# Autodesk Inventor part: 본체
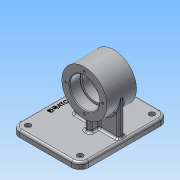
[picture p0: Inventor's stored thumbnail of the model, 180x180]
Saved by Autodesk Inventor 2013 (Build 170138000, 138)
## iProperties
Created: 2019-09
Part Number: 본체
Material: 알루미늄 6061
Document SubType Name: Modeling
Designer: Administrator
Density: 2.71 g/cm^3
Mass: 556.675 g
Surface Area: 495.884 cm^2
Volume: 205.415 cm^3
Author: Administrator
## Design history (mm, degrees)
sketch "스케치1"
  geometry: C1 r 32 at (0, 0); 1 further point
  constraints: 1 centre point, 1 coincident
  dimensions: "d0" = 64 diameter of C1
extrude "돌출1" new body sketch "스케치1" stored distance "d1" = 42; taper "d2" = 0 deg
sketch "스케치2"
  geometry: C1 r 32 at (0, 0) reference; C2 r 21 at (0, 0)
  constraints: 1 centre point, 1 coincident
  dimensions: "d3" = 42 diameter of C2
extrude "돌출2" cut sketch "스케치2" distance "d4" = 15; taper "d5" = 0 deg
sketch "스케치3"
  geometry: C1 r 21 at (0, 0) reference; C2 r 18 at (0, 0)
  constraints: 1 centre point, 1 coincident
  dimensions: "d6" = 36 diameter of C2
extrude "돌출3" cut sketch "스케치3" stored distance "d7" = 15; taper "d8" = 0 deg
sketch "스케치4"
  geometry: C1 r 32 at (0, 0) reference; C2 r 21 at (0, 0)
  constraints: 1 centre point, 1 coincident
  dimensions: "d9" = 42 diameter of C2
extrude "돌출4" cut sketch "스케치4" distance "d10" = 15; taper "d11" = 0 deg
fillet "모깎기1" dims "d12" = 0.3
chamfer "모따기1" distance "d13" = 1; stored, may be unused: second distance "d14" = 2, angle "d15" = 45 deg
sketch "스케치5"
  geometry: C1 r 32 at (0, 0) reference; 1 further point
  constraints: 1 vertical alignment
  dimensions: "d16" = 26 distance of point (0, 26) C1.centre
hole "구멍1" sketch "스케치5" at (0, 26) diameter "d17" = 3.242; stored, may be unused: countersink angle "d21" = 90 deg, drill point angle "d23" = 118 deg; dims "d18" = 8, "d19" = 4, "d20" = 2, "d22" = 10
node "작업 평면1"
sketch "스케치6"
  geometry: L1 (62, -63)-(-36, -63); L2 (-36, -63)-(-36, 63); L3 (-36, 63)-(62, 63); L4 (62, 63)-(62, -63); 1 further point
  constraints: 8 end point, 2 parallel, 1 horizontal, 1 perpendicular
  dimensions: "d28" = 98 distance of L2.end L3.end; "d29" = 126 distance of L1.end L2.end; "d31" = 63 distance from line of point (0, 0) L3; "d32" = 62 distance from line of point (0, 0) L4
extrude "돌출5" join sketch "스케치6" distance "d33" = 9; taper "d34" = 0 deg
fillet "모깎기2" dims "d35" = 12
sketch "스케치7"
  geometry: A1 r 12 centre (-50, -51) between (-62, -51) and (-50, -63) reference; A2 r 12 centre (24, -51) between (24, -63) and (36, -51) reference; A3 r 12 centre (24, 51) between (36, 51) and (24, 63) reference; A4 r 12 centre (-50, 51) between (-50, 63) and (-62, 51) reference; 5 further points
  constraints: 4 coincident
hole "구멍2" sketch "스케치7" at (-50, 51), (24, 51), (-50, -51), (24, -51) diameter "d36" = 4.5; stored, may be unused: countersink angle "d40" = 90 deg, drill point angle "d42" = 118 deg; dims "d37" = 8, "d38" = 8, "d39" = 4.4, "d41" = 9
sketch "스케치8"
  geometry: L1 (4, 17)-(-4, 17); L2 (-4, 17)-(-4, -17); L3 (-4, -17)-(4, -17); L4 (4, -17)-(4, 17); L5 (4, 17)-(-4, -17); L6 (-4, 17)-(4, -17); L7 (32, 4)-(-32, 4); L8 (-32, 4)-(-32, -4); L9 (-32, -4)-(32, -4); L10 (32, -4)-(32, 4); L11 (32, 4)-(-32, -4); L12 (-32, 4)-(32, -4); 1 further point
  constraints: 24 end point, 4 midpoint, 4 parallel, 2 horizontal, 2 perpendicular
  dimensions: "d43" = 8 distance of L3.end L2.end; "d44" = 34 distance of L2.end L1.end; "d45" = 64 distance of L9.end L8.end; "d46" = 8 distance of L8.end L7.end
extrude "돌출6" join sketch "스케치8" stored distance "d47" = 9; taper "d48" = 0 deg
sketch "스케치9"
  geometry: L1 (-62, 51)-(-62, -51) reference; 2 further points
  constraints: 1 horizontal alignment, 1 other
  dimensions: "d49" = 10 distance from line of point (-52, 0) L1
feature "엠보싱1" sketch "스케치9" dims "d50" = 0.5, "d51" = 0
fillet "모깎기3" dims "d52" = 3
fillet "모깎기4" dims "d53" = 3
node "솔리드1"
pattern_circular "원형 패턴1" dims angle "d25" = 360 deg
mirror "대칭1"
other parameters: "d27" = -59
